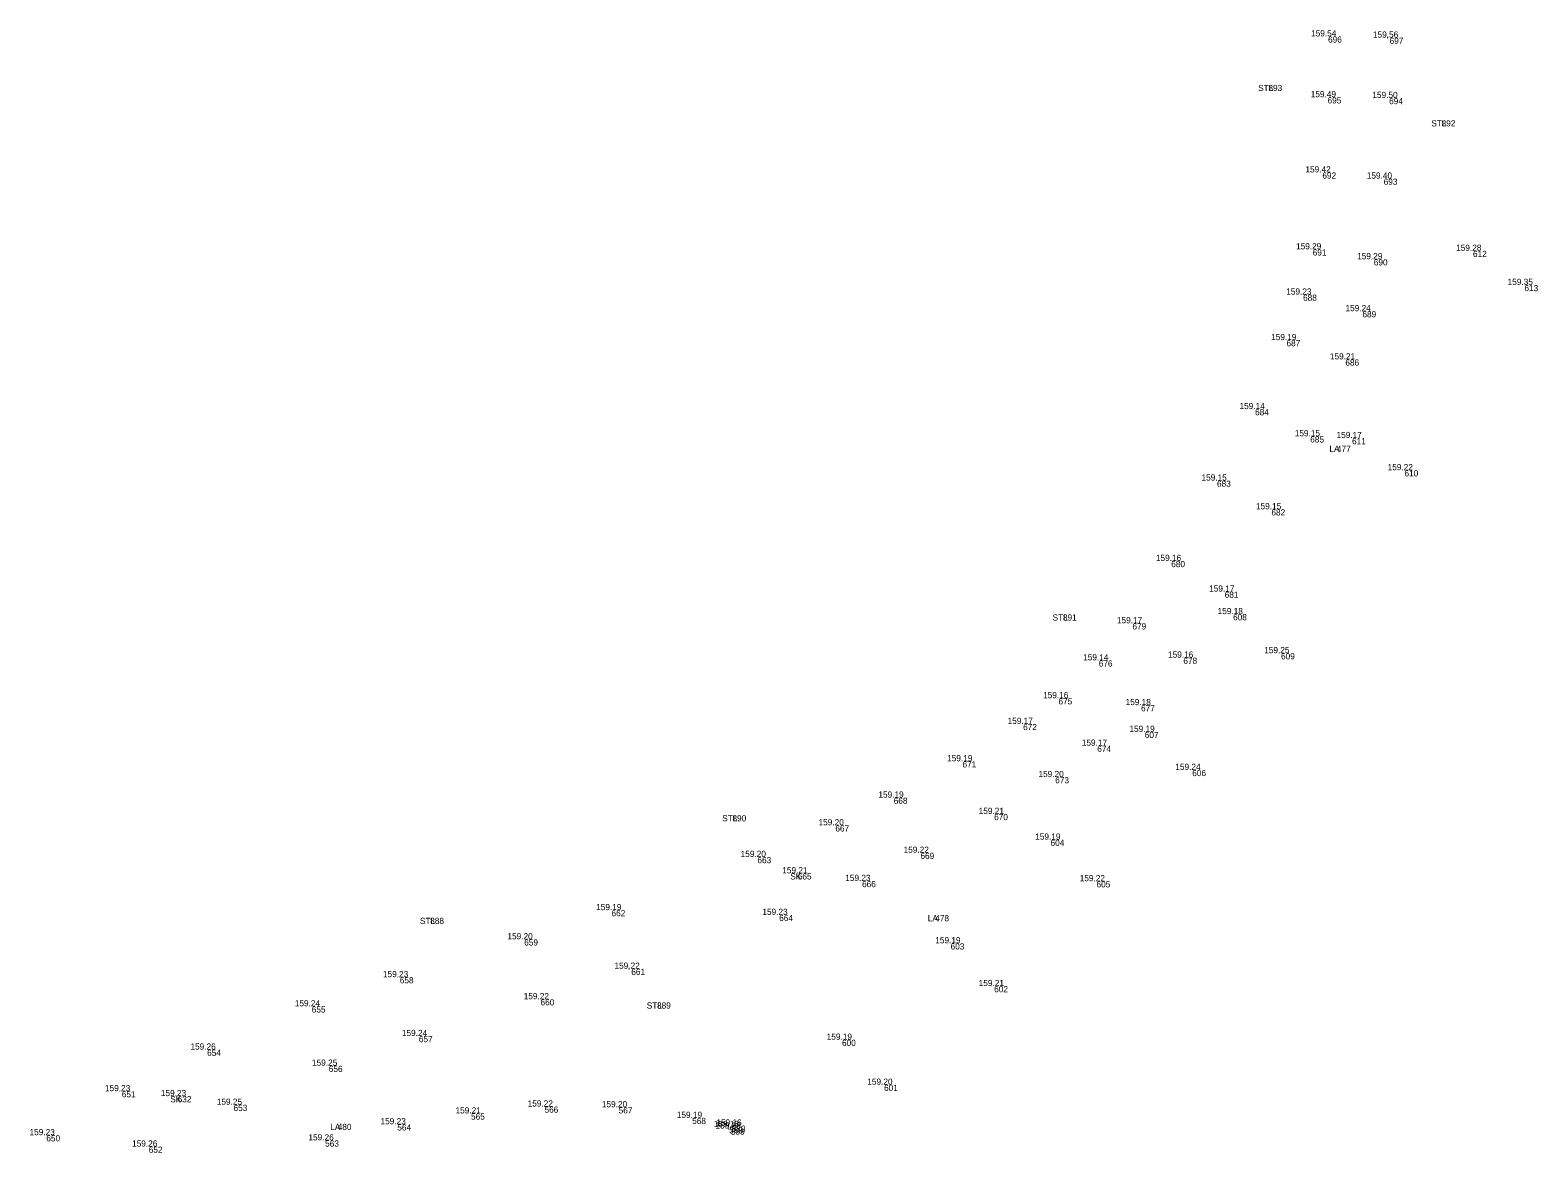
# Model space of a CAD drawing. Extents: x -583198 to -582878, y -1211024 to -1210637.
# Drawn here: x -582959.8 to -582898.9, y -1210831.2 to -1210785.8 of the extents above; entities that cross this region are included whole.
import ezdxf

# ---------------------------------------------------------------- set-up
doc = ezdxf.new("R2010")
doc.units = 0
for name, color, linetype in [('1   Kódy', 7, 'Continuous'), ('4   Body podrobné', 7, 'Continuous'), ('5   Body podrobné - čísla', 7, 'Continuous'), ('6   Body podrobné - výšky', 7, 'Continuous')]:
    doc.layers.add(name, color=color, linetype=linetype)

msp = doc.modelspace()

# ---------------------------------------------------------------- linework, layer by layer
at = {"layer": '4   Body podrobné'}
for p, q in [((-582907.44, -1210786.09), (-582907.439, -1210786.09)), ((-582904.95, -1210786.14), (-582904.949, -1210786.14)), ((-582909.85, -1210788.05), (-582909.849, -1210788.05)), ((-582907.46, -1210788.55), (-582907.459, -1210788.55)), ((-582904.97, -1210788.58), (-582904.969, -1210788.58)), ((-582902.85, -1210789.48), (-582902.849, -1210789.48)), ((-582907.67, -1210791.59), (-582907.669, -1210791.59)), ((-582905.19, -1210791.84), (-582905.189, -1210791.84)), ((-582908.06, -1210794.7), (-582908.059, -1210794.7)), ((-582905.59, -1210795.1), (-582905.589, -1210795.1)), ((-582901.58, -1210794.76), (-582901.579, -1210794.76)), ((-582899.5, -1210796.14), (-582899.499, -1210796.14)), ((-582908.45, -1210796.53), (-582908.449, -1210796.53)), ((-582906.05, -1210797.2), (-582906.049, -1210797.2)), ((-582909.12, -1210798.37), (-582909.119, -1210798.37)), ((-582906.74, -1210799.15), (-582906.739, -1210799.15)), ((-582910.39, -1210801.16), (-582910.389, -1210801.16)), ((-582908.16, -1210802.26), (-582908.159, -1210802.26)), ((-582906.47, -1210802.33), (-582906.469, -1210802.33)), ((-582907.08, -1210802.64), (-582907.079, -1210802.64)), ((-582904.35, -1210803.63), (-582904.349, -1210803.63)), ((-582911.93, -1210804.05), (-582911.929, -1210804.05)), ((-582909.73, -1210805.21), (-582909.729, -1210805.21)), ((-582913.78, -1210807.3), (-582913.779, -1210807.3)), ((-582911.62, -1210808.54), (-582911.619, -1210808.54)), ((-582918.16, -1210809.46), (-582918.159, -1210809.46)), ((-582915.35, -1210809.82), (-582915.349, -1210809.82)), ((-582911.28, -1210809.45), (-582911.279, -1210809.45)), ((-582909.34, -1210811.03), (-582909.339, -1210811.03)), ((-582916.71, -1210811.32), (-582916.709, -1210811.32)), ((-582913.29, -1210811.21), (-582913.289, -1210811.21)), ((-582918.34, -1210812.85), (-582918.339, -1210812.85)), ((-582915, -1210813.13), (-582914.999, -1210813.13)), ((-582919.77, -1210813.89), (-582919.769, -1210813.89)), ((-582914.85, -1210814.21), (-582914.849, -1210814.21)), ((-582916.77, -1210814.77), (-582916.769, -1210814.77)), ((-582922.22, -1210815.4), (-582922.219, -1210815.4)), ((-582912.93, -1210815.75), (-582912.929, -1210815.75)), ((-582918.47, -1210816.04), (-582918.469, -1210816.04)), ((-582925, -1210816.87), (-582924.999, -1210816.87)), ((-582931.52, -1210817.58), (-582931.519, -1210817.58)), ((-582920.94, -1210817.53), (-582920.939, -1210817.53)), ((-582927.36, -1210817.99), (-582927.359, -1210817.99)), ((-582918.66, -1210818.57), (-582918.659, -1210818.57)), ((-582930.51, -1210819.27), (-582930.509, -1210819.27)), ((-582923.92, -1210819.1), (-582923.919, -1210819.1)), ((-582928.88, -1210819.93), (-582928.879, -1210819.93)), ((-582926.28, -1210820.24), (-582926.279, -1210820.24)), ((-582916.8, -1210820.25), (-582916.799, -1210820.25)), ((-582936.41, -1210821.42), (-582936.409, -1210821.42)), ((-582943.74, -1210821.73), (-582943.739, -1210821.73)), ((-582929.63, -1210821.61), (-582929.629, -1210821.61)), ((-582923.32, -1210821.62), (-582923.319, -1210821.62)), ((-582939.94, -1210822.6), (-582939.939, -1210822.6)), ((-582922.7, -1210822.76), (-582922.699, -1210822.76)), ((-582935.61, -1210823.79), (-582935.609, -1210823.79)), ((-582944.97, -1210824.13), (-582944.969, -1210824.13)), ((-582920.94, -1210824.49), (-582920.939, -1210824.49)), ((-582939.28, -1210825.02), (-582939.279, -1210825.02)), ((-582948.53, -1210825.31), (-582948.529, -1210825.31)), ((-582934.57, -1210825.15), (-582934.569, -1210825.15)), ((-582944.2, -1210826.51), (-582944.199, -1210826.51)), ((-582927.09, -1210826.66), (-582927.089, -1210826.66)), ((-582952.76, -1210827.06), (-582952.759, -1210827.06)), ((-582947.84, -1210827.71), (-582947.839, -1210827.71)), ((-582956.21, -1210828.74), (-582956.209, -1210828.74)), ((-582925.39, -1210828.48), (-582925.389, -1210828.48)), ((-582953.95, -1210828.94), (-582953.949, -1210828.94)), ((-582951.69, -1210829.29), (-582951.689, -1210829.29)), ((-582939.12, -1210829.36), (-582939.119, -1210829.36)), ((-582942.09, -1210829.64), (-582942.089, -1210829.64)), ((-582936.12, -1210829.39), (-582936.119, -1210829.39)), ((-582933.15, -1210829.82), (-582933.149, -1210829.82)), ((-582959.26, -1210830.52), (-582959.259, -1210830.52)), ((-582947.48, -1210830.06), (-582947.479, -1210830.06)), ((-582945.07, -1210830.08), (-582945.069, -1210830.08)), ((-582931.65, -1210830.19), (-582931.649, -1210830.19)), ((-582931.58, -1210830.25), (-582931.579, -1210830.25)), ((-582931.55, -1210830.13), (-582931.549, -1210830.13)), ((-582955.12, -1210830.98), (-582955.119, -1210830.98)), ((-582947.99, -1210830.73), (-582947.989, -1210830.73))]:
    msp.add_line(p, q, dxfattribs=at)

# ---------------------------------------------------------------- texts
at = {"layer": '1   Kódy'}
for s, p in [('STL', (-582910.172, -1210788.3)), ('STL', (-582903.172, -1210789.73)), ('LA', (-582907.29, -1210802.89)), ('STL', (-582918.482, -1210809.71)), ('STL', (-582931.842, -1210817.83)), ('SK', (-582929.089, -1210820.18)), ('STL', (-582944.062, -1210821.98)), ('LA', (-582923.53, -1210821.87)), ('STL', (-582934.892, -1210825.4)), ('SK', (-582954.159, -1210829.19)), ('LA', (-582947.69, -1210830.31))]:
    msp.add_text(s, height=0.25, dxfattribs=at).set_placement(p)
at = {"layer": '5   Body podrobné - čísla'}
for s, p in [(' 696', (-582907.44, -1210786.34)), (' 697', (-582904.95, -1210786.39)), (' 893', (-582909.85, -1210788.3)), (' 695', (-582907.46, -1210788.8)), (' 694', (-582904.97, -1210788.83)), (' 892', (-582902.85, -1210789.73)), (' 692', (-582907.67, -1210791.84)), (' 693', (-582905.19, -1210792.09)), (' 691', (-582908.06, -1210794.95)), (' 690', (-582905.59, -1210795.35)), (' 612', (-582901.58, -1210795.01)), (' 613', (-582899.5, -1210796.39)), (' 688', (-582908.45, -1210796.78)), (' 689', (-582906.05, -1210797.45)), (' 687', (-582909.12, -1210798.62)), (' 686', (-582906.74, -1210799.4)), (' 684', (-582910.39, -1210801.41)), (' 685', (-582908.16, -1210802.51)), (' 611', (-582906.47, -1210802.58)), (' 477', (-582907.08, -1210802.89)), (' 610', (-582904.35, -1210803.88)), (' 683', (-582911.93, -1210804.3)), (' 682', (-582909.73, -1210805.46)), (' 680', (-582913.78, -1210807.55)), (' 681', (-582911.62, -1210808.79)), (' 891', (-582918.16, -1210809.71)), (' 679', (-582915.35, -1210810.07)), (' 608', (-582911.28, -1210809.7)), (' 609', (-582909.34, -1210811.28)), (' 676', (-582916.71, -1210811.57)), (' 678', (-582913.29, -1210811.46)), (' 675', (-582918.34, -1210813.1)), (' 677', (-582915, -1210813.38)), (' 672', (-582919.77, -1210814.14)), (' 607', (-582914.85, -1210814.46)), (' 674', (-582916.77, -1210815.02)), (' 671', (-582922.22, -1210815.65)), (' 606', (-582912.93, -1210816)), (' 673', (-582918.47, -1210816.29)), (' 668', (-582925, -1210817.12)), (' 890', (-582931.52, -1210817.83)), (' 670', (-582920.94, -1210817.78)), (' 667', (-582927.36, -1210818.24)), (' 604', (-582918.66, -1210818.82)), (' 663', (-582930.51, -1210819.52)), (' 669', (-582923.92, -1210819.35)), (' 665', (-582928.88, -1210820.18)), (' 666', (-582926.28, -1210820.49)), (' 605', (-582916.8, -1210820.5)), (' 662', (-582936.41, -1210821.67)), (' 888', (-582943.74, -1210821.98)), (' 664', (-582929.63, -1210821.86)), (' 478', (-582923.32, -1210821.87)), (' 659', (-582939.94, -1210822.85)), (' 603', (-582922.7, -1210823.01)), (' 661', (-582935.61, -1210824.04)), (' 658', (-582944.97, -1210824.38)), (' 602', (-582920.94, -1210824.74)), (' 660', (-582939.28, -1210825.27)), (' 655', (-582948.53, -1210825.56)), (' 889', (-582934.57, -1210825.4)), (' 657', (-582944.2, -1210826.76)), (' 600', (-582927.09, -1210826.91)), (' 654', (-582952.76, -1210827.31)), (' 656', (-582947.84, -1210827.96)), (' 651', (-582956.21, -1210828.99)), (' 601', (-582925.39, -1210828.73)), (' 632', (-582953.95, -1210829.19)), (' 653', (-582951.69, -1210829.54)), (' 566', (-582939.12, -1210829.61)), (' 565', (-582942.09, -1210829.89)), (' 567', (-582936.12, -1210829.64)), (' 568', (-582933.15, -1210830.07)), (' 650', (-582959.26, -1210830.77)), (' 480', (-582947.48, -1210830.31)), (' 564', (-582945.07, -1210830.33)), (' 569', (-582931.65, -1210830.44)), (' 599', (-582931.58, -1210830.5)), (' 570', (-582931.55, -1210830.38)), (' 652', (-582955.12, -1210831.23)), (' 563', (-582947.99, -1210830.98))]:
    msp.add_text(s, height=0.25, dxfattribs=at).set_placement(p)
at = {"layer": '6   Body podrobné - výšky'}
for s, p in [('159.54', (-582908.032, -1210786.09)), ('159.56', (-582905.531, -1210786.14)), ('159.49', (-582908.047, -1210788.55)), ('159.50', (-582905.556, -1210788.58)), ('159.42', (-582908.262, -1210791.59)), ('159.40', (-582905.781, -1210791.84)), ('159.29', (-582908.641, -1210794.7)), ('159.28', (-582902.167, -1210794.76)), ('159.29', (-582906.171, -1210795.1)), ('159.23', (-582909.037, -1210796.53)), ('159.35', (-582900.087, -1210796.14)), ('159.24', (-582906.642, -1210797.2)), ('159.19', (-582909.647, -1210798.37)), ('159.21', (-582907.272, -1210799.15)), ('159.14', (-582910.928, -1210801.16)), ('159.15', (-582908.692, -1210802.26)), ('159.17', (-582907.003, -1210802.33)), ('159.22', (-582904.937, -1210803.63)), ('159.15', (-582912.462, -1210804.05)), ('159.15', (-582910.262, -1210805.21)), ('159.16', (-582914.307, -1210807.3)), ('159.17', (-582912.153, -1210808.54)), ('159.18', (-582911.812, -1210809.45)), ('159.17', (-582915.883, -1210809.82)), ('159.14', (-582917.248, -1210811.32)), ('159.16', (-582913.817, -1210811.21)), ('159.25', (-582909.927, -1210811.03)), ('159.16', (-582918.867, -1210812.85)), ('159.18', (-582915.532, -1210813.13)), ('159.17', (-582920.303, -1210813.89)), ('159.19', (-582915.377, -1210814.21)), ('159.17', (-582917.303, -1210814.77)), ('159.19', (-582922.747, -1210815.4)), ('159.20', (-582919.056, -1210816.04)), ('159.24', (-582913.522, -1210815.75)), ('159.19', (-582925.527, -1210816.87)), ('159.20', (-582927.946, -1210817.99)), ('159.21', (-582921.472, -1210817.53)), ('159.19', (-582919.187, -1210818.57)), ('159.22', (-582924.507, -1210819.1)), ('159.20', (-582931.096, -1210819.27)), ('159.21', (-582929.412, -1210819.93)), ('159.23', (-582926.867, -1210820.24)), ('159.22', (-582917.387, -1210820.25)), ('159.19', (-582936.937, -1210821.42)), ('159.23', (-582930.217, -1210821.61)), ('159.20', (-582940.526, -1210822.6)), ('159.19', (-582923.227, -1210822.76)), ('159.23', (-582945.557, -1210824.13)), ('159.22', (-582936.197, -1210823.79)), ('159.21', (-582921.472, -1210824.49)), ('159.24', (-582949.122, -1210825.31)), ('159.22', (-582939.867, -1210825.02)), ('159.24', (-582944.792, -1210826.51)), ('159.26', (-582953.341, -1210827.06)), ('159.19', (-582927.617, -1210826.66)), ('159.25', (-582948.427, -1210827.71)), ('159.23', (-582956.797, -1210828.74)), ('159.23', (-582954.537, -1210828.94)), ('159.20', (-582925.976, -1210828.48)), ('159.25', (-582952.277, -1210829.29)), ('159.22', (-582939.707, -1210829.36)), ('159.20', (-582936.706, -1210829.39)), ('159.23', (-582945.657, -1210830.08)), ('159.21', (-582942.622, -1210829.64)), ('159.19', (-582933.677, -1210829.82)), ('159.18', (-582932.182, -1210830.19)), ('159.16', (-582932.077, -1210830.13)), ('159.23', (-582959.847, -1210830.52)), ('159.26', (-582948.571, -1210830.73)), ('159.18', (-582932.112, -1210830.25)), ('159.26', (-582955.701, -1210830.98))]:
    msp.add_text(s, height=0.25, dxfattribs=at).set_placement(p)

doc.saveas('drawing.dxf')
